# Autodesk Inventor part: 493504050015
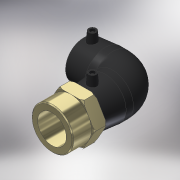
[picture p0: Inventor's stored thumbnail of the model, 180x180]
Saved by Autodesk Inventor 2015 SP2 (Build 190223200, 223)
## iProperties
Created: 2017-06
Part Number: 493504050015
Material: Generic
Description: PLASSON 90° ELBOW FEMALE TRANSITION 50-1.1/2''
Document SubType Name: Modeling
Designer: KIM
Mass: 312.073 g
Surface Area: 682.137 cm^2
Volume: 312.073 cm^3
Density: 1 g/cm^3
Appearance: Rubber - Black
Author: KIM
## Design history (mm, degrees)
derived "493504.ipt"
feature "Solid1::493504.ipt"
tag "TaggingFeature1"
body "Solid1"
other parameters: "d2" = 67, "d4" = 36, "d5" = 60.3, "d8" = 168 deg, "d10" = 19.2, "d11" = 6.4, "d29" = 52, "d30" = 15, "d31" = 59.4, "d34" = 5 deg, "d41" = 4, "d42" = 14, "d43" = 0, "d48" = 74.5, "d50" = 42.5, "d51" = 19.2, "d52" = 48, "d54" = 90 deg, "d58" = 48, "d59" = 0, "d61" = 90 deg, "d86" = 3, "d87" = 0, "d93" = 0.1, "d96" = 44.845, "d97" = 38, "d98" = 25, "d99" = 67, "d108" = 0, "d109" = 1.5, "d112" = 45 deg, "d113" = 45 deg, "d114" = 2.5, "L_" = 133, "L_1" = 48, "D_" = 38, "A_" = 52, "d_2" = 12, "L_2" = 25, "D_1" = 67, "Rp_" = 44.845
